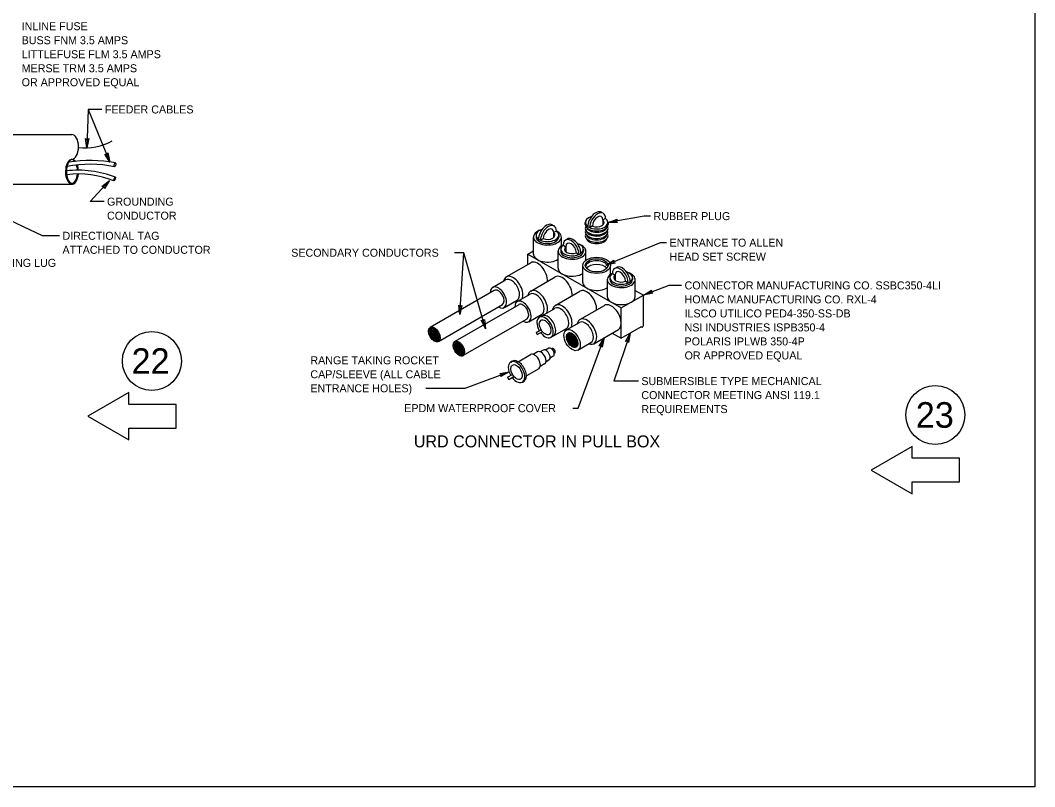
# Model space of a CAD drawing. Extents: x 99981 to 128681, y 99783 to 102182.
# Drawn here: x 127161 to 128681, y 99887 to 101036 of the extents above; entities that cross this region are included whole.
import ezdxf

# ---------------------------------------------------------------- set-up
doc = ezdxf.new("R2010")
doc.units = 0
for name, color, linetype in [('Default', 7, 'Continuous'), ('Level 1', 7, 'Continuous'), ('RD Lighting', 7, 'Continuous')]:
    doc.layers.add(name, color=color, linetype=linetype)

msp = doc.modelspace()

# ---------------------------------------------------------------- linework, layer by layer
at = {"layer": 'Default'}
msp.add_lwpolyline([(125481.4, 102086.3), (128681.1, 102086.3), (128681.1, 99886.7), (125481.4, 99886.7)], close=True, dxfattribs=at)
at = {"layer": 'Level 1'}
for p, q in [((127262.2, 100902.4), (127260.4, 100844.8)), ((127262.2, 100902.4), (127294.8, 100823.1)), ((127282.9, 100902.4), (127262.2, 100902.4)), ((127142.6, 100864.8), (127238.1, 100864.8)), ((127142.6, 100790.3), (127238.1, 100790.3)), ((127265.4, 100764.1), (127294.3, 100795.7)), ((127194, 100712.9), (127081.9, 100765.7)), ((127286.1, 100764.1), (127265.4, 100764.1)), ((128007.4, 100730), (128007.4, 100732.9)), ((128037.8, 100739), (128033.8, 100736.6)), ((128033.8, 100736.6), (128033.8, 100729.1)), ((128095.9, 100742.4), (128041.5, 100732.9)), ((128041.5, 100732.9), (128041.5, 100730)), ((128105.3, 100742.4), (128095.9, 100742.4)), ((127964.1, 100720.1), (127960, 100717.7)), ((127960, 100717.7), (127960, 100710.2)), ((128018, 100727.5), (128014, 100725.1)), ((127219.4, 100712.9), (127194, 100712.9)), ((127929.9, 100685.6), (127929.9, 100711.1)), ((127933.7, 100714), (127933.7, 100711.1)), ((127944.3, 100708.6), (127940.2, 100706.2)), ((127967.8, 100714), (127967.8, 100711.1)), ((127971.6, 100697.6), (127971.6, 100711.1)), ((128119.8, 100702.6), (128038.1, 100668.8)), ((128129.3, 100702.6), (128119.8, 100702.6)), ((127825.2, 100687.5), (127811.2, 100687.5)), ((127819.3, 100594.7), (127825.2, 100687.5)), ((127857.8, 100573.3), (127825.2, 100687.5)), ((127921.3, 100685.6), (127929.9, 100690.5)), ((127921.3, 100670), (127921.3, 100685.6)), ((127921.3, 100685.6), (128061.4, 100604.7)), ((127966.7, 100664.3), (127966.7, 100689.8)), ((127970.6, 100692.7), (127970.6, 100689.8)), ((127974.2, 100698.7), (127978.3, 100696.4)), ((127978.3, 100696.4), (127978.3, 100689)), ((127994.1, 100687.3), (127998.1, 100685)), ((128004.6, 100692.7), (128004.6, 100689.8)), ((128008.5, 100676.3), (128008.5, 100689.8)), ((127888.7, 100651.2), (127925.6, 100672.4)), ((128003.6, 100643), (128003.6, 100668.6)), ((128045.3, 100655), (128045.3, 100668.6)), ((128048, 100656.2), (128052.1, 100653.8)), ((128052.1, 100653.8), (128052.1, 100646.4)), ((127868.4, 100635.4), (127888, 100646.7)), ((127925.6, 100629.9), (127962.4, 100651.2)), ((128040.5, 100621.7), (128040.5, 100647.3)), ((128044.3, 100650.1), (128044.3, 100647.3)), ((128067.8, 100644.7), (128071.9, 100642.4)), ((128078.4, 100650.1), (128078.4, 100647.3)), ((128082.2, 100621.7), (128082.2, 100647.3)), ((128132.9, 100638.5), (128094.5, 100623.9)), ((128151.8, 100638.5), (128132.9, 100638.5)), ((127871, 100630.9), (127775.1, 100575.6)), ((127905.4, 100614.2), (127924.8, 100625.4)), ((127962.4, 100608.6), (127999.3, 100629.9)), ((128061.4, 100604.7), (128094.5, 100623.9)), ((128082.2, 100631), (128094.5, 100623.9)), ((128094.5, 100578.5), (128094.5, 100623.9)), ((127787.3, 100554.5), (127883.2, 100609.8)), ((127907.9, 100609.6), (127811.9, 100554.3)), ((127886.2, 100605.6), (127905.3, 100616.6)), ((127999.3, 100587.3), (128036.2, 100608.6)), ((127922.7, 100584.1), (127942.2, 100595.3)), ((127938.5, 100590.7), (127941.7, 100592.6)), ((127942.5, 100593), (127961.7, 100604.1)), ((128061.4, 100559.3), (128061.4, 100604.7)), ((127824.1, 100533.2), (127920.1, 100588.5)), ((127979.3, 100571.7), (127998.6, 100582.9)), ((127933.7, 100567.9), (127941.1, 100572.2)), ((127933.7, 100567.9), (127935.5, 100564.9)), ((127935.5, 100564.9), (127943.1, 100569.3)), ((127955.9, 100560.7), (127959.9, 100563)), ((127959.9, 100563), (127979.1, 100574)), ((128020.2, 100551.1), (128057.1, 100572.4)), ((128047.9, 100567.1), (128061.4, 100559.3)), ((128074.7, 100567), (128050.1, 100495)), ((128061.4, 100559.3), (128091.7, 100576.9)), ((127996.5, 100541.6), (128016, 100552.8)), ((127996.9, 100454.4), (128035.5, 100560)), ((127907, 100524), (127925.4, 100534.7)), ((127936, 100538.8), (127929.4, 100535)), ((127944.3, 100541.5), (127939.9, 100538.9)), ((127952.6, 100544.3), (127947.8, 100541.5)), ((127959.5, 100532.2), (127954.7, 100529.5)), ((127957.8, 100543.7), (127957.1, 100543.2)), ((127961.6, 100537.1), (127960.8, 100536.6)), ((127895.7, 100523.5), (127898.2, 100524.9)), ((127946.5, 100520.7), (127939.8, 100516.8)), ((127953, 100526.5), (127948.6, 100523.9)), ((127827.2, 100484.2), (127893.2, 100509.1)), ((127891, 100500.7), (127898.3, 100505)), ((127892.8, 100497.6), (127900.4, 100502)), ((127937.6, 100513.5), (127919.2, 100502.9)), ((127891, 100500.7), (127892.8, 100497.6)), ((127913.1, 100493.4), (127915.6, 100494.9)), ((128087, 100495), (128050.1, 100495)), ((127768.4, 100484.2), (127827.2, 100484.2)), ((127988.7, 100454.4), (127996.9, 100454.4))]:
    msp.add_line(p, q, dxfattribs=at)
for points in [[(127263.2, 100858.8), (127260.4, 100844.8), (127258.5, 100859), (127260.8, 100856.7)], [(127291.7, 100837.1), (127294.8, 100823.1), (127287.2, 100835.3), (127290.3, 100834.1)], [(127283, 100786.9), (127294.3, 100795.7), (127286.6, 100783.7), (127286.3, 100786.9)], [(128055.8, 100732.9), (128041.5, 100732.9), (128055, 100737.7), (128053.2, 100734.9)], [(128052, 100672), (128038.1, 100668.8), (128050.2, 100676.4), (128049.1, 100673.4)], [(128108.6, 100626.7), (128094.5, 100623.9), (128106.9, 100631.2), (128105.7, 100628.1)], [(127822.6, 100608.6), (127819.3, 100594.7), (127817.8, 100608.9), (127820, 100606.6)], [(127856.2, 100587.5), (127857.8, 100573.3), (127851.6, 100586.2), (127854.5, 100584.8)], [(128067.9, 100554.4), (128074.7, 100567), (128072.4, 100552.8), (128070.8, 100555.7)], [(128028.4, 100547.5), (128035.5, 100560), (128032.9, 100545.9), (128031.4, 100548.8)], [(127879.2, 100506.4), (127893.2, 100509.1), (127880.9, 100501.9), (127882.1, 100504.9)]]:
    msp.add_lwpolyline(points, close=True, dxfattribs=at)
for centre, radius, start, end in [((127256.7, 100932.6), 87.8, 264.2056, 298.4266), ((127242.7, 100817.2), 11.4, 113.762, 165.0443), ((127265, 100627.8), 198, 78.9111, 99.2947), ((127233.4, 100817), 11.6, 39.1129, 65.8989), ((127247.5, 100660.4), 150.9, 68.3519, 96.7966), ((127247.5, 100660.4), 145.2, 68.3519, 96.856), ((127265, 100627.8), 192.3, 78.9111, 100.276)]:
    msp.add_arc(centre, radius, start, end, dxfattribs=at)
for centre, major_axis, ratio, start_param, end_param in [((127238.1, 100846.3), (0, 18.6), 0.524286, 3.150248, 6.285615), ((127238.1, 100809), (0, 18.6), 0.524286, 5.69971, 10.802617), ((127238.1, 100809), (0, 17.3), 0.486783, 0.869952, 4.499875), ((127238.1, 100809), (0, 17.3), 0.486783, 4.849199, 5.309813), ((127238.1, 100809), (0, 18.6), 0.524286, 4.829653, 5.277118), ((128023.1, 100733.7), (8.4, 14.6), 0.57735, 6.113683, 8.6437), ((128025.9, 100732), (8.4, 14.6), 0.57735, 5.500907, 8.642499), ((127949.3, 100714.8), (8.4, 14.6), 0.57735, 6.113683, 8.6437), ((128024.5, 100732.9), (17, 0), 0.57735, 2.043723, 6.953551), ((128024.5, 100730), (17, 0), 0.57735, 3.141593, 6.283185), ((128025.9, 100732), (5.56, 9.63), 0.57735, 5.501145, 8.639609), ((128024.5, 100732.9), (11.3, 0), 0.57735, 4.106085, 6.89307), ((127950.7, 100711.1), (20.9, 0), 0.57735, 2.164315, 7.164292), ((127950.7, 100714), (17, 0), 0.57735, 2.032674, 6.953551), ((127952.2, 100713.1), (8.4, 14.6), 0.57735, 5.500907, 8.642499), ((127952.2, 100713.1), (5.56, 9.63), 0.57735, 5.501145, 8.639609), ((127950.7, 100714), (11.3, 0), 0.57735, 4.106085, 6.89307), ((128024.5, 100718.7), (17, 0), 0.57735, 2.836673, 6.549804), ((128024.5, 100713), (17, 0), 0.57735, 2.848328, 6.575909), ((128024.5, 100724.3), (17, 0), 0.57735, 2.868704, 6.55622), ((128024.5, 100721.5), (15.6, 0), 0.57735, 3.248585, 6.145478), ((128024.5, 100715.8), (15.6, 0), 0.57735, 3.261904, 6.162161), ((128024.5, 100727.2), (15.6, 0), 0.57735, 3.313023, 6.148611), ((127950.7, 100711.1), (17, 0), 0.57735, 3.141593, 6.283185), ((127950.7, 100711.1), (17, 0), 0.57735, 3.004539, 3.005199), ((127987.6, 100689.8), (20.9, 0), 0.57735, 2.27457, 7.247643), ((127987.6, 100692.7), (17, 0), 0.57735, 2.474262, 7.371716), ((127986.2, 100691.9), (-8.4, 14.6), 0.57735, 3.927123, 7.068716), ((127986.2, 100691.9), (-5.56, 9.63), 0.57735, 3.92676, 7.068352), ((127989.1, 100693.5), (-8.4, 14.6), 0.57735, 3.927123, 6.458478), ((128024.5, 100710.2), (15.6, 0), 0.57735, 3.270531, 6.142887), ((127950.7, 100685.6), (20.9, 0), 0.57735, 3.141593, 5.586889), ((127987.6, 100689.8), (17, 0), 0.57735, 3.141593, 6.283185), ((127987.6, 100689.8), (17, 0), 0.57735, 3.004539, 3.005199), ((127987.6, 100692.7), (11.3, 0), 0.57735, 2.534527, 5.318723), ((127936, 100654.4), (-10.4, 18.1), 0.57735, 3.840254, 6.28365), ((128024.5, 100668.6), (17, 0), 0.57735, 3.004539, 3.005199), ((128024.5, 100665.7), (17, 0), 0.57735, 0.137713, 2.968876), ((128024.5, 100660), (17, 0), 0.57735, 0.449551, 2.696225), ((127899.2, 100633.1), (-10.4, 18.1), 0.57735, 3.511299, 6.867888), ((127972.9, 100633.1), (-10.4, 18.1), 0.57735, 3.840254, 6.28365), ((127987.6, 100664.3), (20.9, 0), 0.57735, 3.141593, 5.586889), ((128061.3, 100647.3), (20.9, 0), 0.57735, 2.26416, 7.252802), ((128061.3, 100650.1), (17, 0), 0.57735, 2.474262, 7.371716), ((128059.9, 100649.3), (-8.4, 14.6), 0.57735, 3.927123, 7.068716), ((128061.3, 100650.1), (11.3, 0), 0.57735, 2.534527, 5.318723), ((128059.9, 100649.3), (-5.56, 9.63), 0.57735, 3.92676, 7.068352), ((128062.8, 100650.9), (-8.4, 14.6), 0.57735, 3.927123, 6.458478), ((127896.7, 100631.7), (-8.7, 15.1), 0.57735, 3.132798, 6.291946), ((128024.5, 100643), (20.9, 0), 0.57735, 3.141593, 5.586889), ((128061.3, 100647.3), (17, 0), 0.57735, 3.141593, 6.283185), ((128061.3, 100647.3), (17, 0), 0.57735, 3.004539, 3.005199), ((127877.1, 100620.4), (-8.7, 15.1), 0.57735, 2.332703, 7.093606), ((127877.1, 100620.4), (-6.1, 10.6), 0.57735, 3.142382, 6.283974), ((127936, 100611.8), (-10.4, 18.1), 0.57735, 3.511299, 6.867888), ((127933.6, 100610.4), (-8.7, 15.1), 0.57735, 3.132798, 6.291946), ((128009.7, 100611.8), (-10.4, 18.1), 0.57735, 3.837363, 6.28365), ((127914, 100599.1), (-8.7, 15.1), 0.57735, 2.369926, 7.104852), ((127899.2, 100633.1), (-10.4, 18.1), 0.57735, 2.550847, 2.771598), ((127914, 100599.1), (-6.1, 10.6), 0.57735, 3.142382, 6.283974), ((127972.9, 100590.5), (-10.4, 18.1), 0.57735, 3.509514, 6.867888), ((128046.6, 100590.5), (-10.4, 18.1), 0.57735, 3.142057, 6.28365), ((128061.3, 100621.7), (20.9, 0), 0.57735, 3.141593, 6.283185), ((127947.2, 100575.7), (-8.7, 15.1), 0.57735, 1.776655, 7.854029), ((127936, 100611.8), (-10.4, 18.1), 0.57735, 2.550847, 2.771598), ((127950.8, 100577.8), (-8.7, 15.1), 0.57735, 3.190548, 6.332665), ((127970.5, 100589.1), (-8.7, 15.1), 0.57735, 3.132798, 6.291946), ((128009.8, 100569.2), (-10.4, 18.1), 0.57735, 2.552288, 6.869338), ((128007.3, 100567.8), (-8.7, 15.1), 0.57735, 3.141603, 6.283196), ((128093.1, 100577.7), (1, 1.74), 0.57735, 2.358489, 5.500082), ((127972.9, 100590.5), (-10.4, 18.1), 0.57735, 2.550847, 2.771598), ((127988.9, 100557.2), (-6.1, 10.6), 0.57735, 0.118401, 3.033391), ((127990.1, 100557.9), (-6.1, 10.6), 0.57735, 0.206652, 2.965468), ((127991.4, 100558.6), (-6.1, 10.6), 0.57735, 0.326201, 2.848852), ((127992.6, 100559.3), (-6.1, 10.6), 0.57735, 0.426417, 2.720117), ((127993.8, 100560.1), (-6.1, 10.6), 0.57735, 0.536288, 2.627234), ((127995.1, 100560.8), (-6.1, 10.6), 0.57735, 0.645059, 2.50346), ((127996.3, 100561.5), (-6.1, 10.6), 0.57735, 0.775948, 2.37161), ((127997.5, 100562.2), (-6.1, 10.6), 0.57735, 0.931064, 2.211843), ((127998.8, 100562.9), (-6.1, 10.6), 0.57735, 1.123825, 2.025294), ((127931.5, 100524.1), (-6.1, 10.6), 0.57735, 3.142382, 6.283974), ((127941.3, 100529.7), (-5.24, 9.07), 0.57735, 3.142596, 6.284189), ((127948.7, 100534), (-4.33, 7.51), 0.57735, 3.141603, 6.283196), ((127956.1, 100538.3), (-3.47, 6.01), 0.57735, 3.139149, 6.280742), ((127959.7, 100540.4), (-1.91, 3.3), 0.57735, 3.141901, 6.283494), ((127904.4, 100508.5), (-8.7, 15.1), 0.57735, 1.776655, 7.854029), ((127906.9, 100509.9), (-8.7, 15), 0.57735, 3.141603, 6.283196)]:
    msp.add_ellipse(centre, major_axis=major_axis, ratio=ratio, start_param=start_param, end_param=end_param, dxfattribs=at)
for centre, major_axis, ratio in [((127302.5, 100819.3), (-0.51, -2.82), 0.388202), ((127302.1, 100798), (1.05, 2.64), 0.311921), ((128024.5, 100668.6), (20.9, 0), 0.57735), ((128024.5, 100668.6), (17, 0), 0.57735), ((127781.2, 100565), (-6.1, 10.6), 0.57735), ((127947.2, 100575.7), (-6.1, 10.6), 0.57735), ((127774.7, 100569.9), (-0.78, 1.34), 0.57735), ((127774.8, 100566.7), (-0.78, 1.34), 0.57735), ((127775.8, 100572.4), (-0.78, 1.34), 0.57735), ((127776.7, 100561.2), (-0.78, 1.34), 0.57735), ((127776.9, 100564.1), (-0.78, 1.34), 0.57735), ((127777.2, 100566.7), (-0.78, 1.34), 0.57735), ((127777.8, 100573.9), (-0.78, 1.34), 0.57735), ((127778.2, 100569.7), (-0.78, 1.34), 0.57735), ((127778.9, 100560.5), (-0.78, 1.34), 0.57735), ((127779.5, 100563.1), (-0.78, 1.34), 0.57735), ((127780, 100565.7), (-0.78, 1.34), 0.57735), ((127780.5, 100570.6), (-0.78, 1.34), 0.57735), ((127780.9, 100573.3), (-0.78, 1.34), 0.57735), ((127781.5, 100568), (-0.78, 1.34), 0.57735), ((127781.5, 100561.5), (-0.78, 1.34), 0.57735), ((127782.4, 100565.2), (-0.78, 1.34), 0.57735), ((127783, 100568.2), (-0.78, 1.34), 0.57735), ((127783.3, 100563), (-0.78, 1.34), 0.57735), ((127783.8, 100570.6), (-0.78, 1.34), 0.57735), ((127784.4, 100564.9), (-0.78, 1.34), 0.57735), ((127785.7, 100561.4), (-0.78, 1.34), 0.57735), ((127786.1, 100567.6), (-0.78, 1.34), 0.57735), ((127786.8, 100563.9), (-0.78, 1.34), 0.57735), ((127788.2, 100560.8), (-0.78, 1.34), 0.57735), ((127987.7, 100556.5), (-8.7, 15.1), 0.57735), ((127987.7, 100556.5), (-6.1, 10.6), 0.57735), ((127779.8, 100557.6), (-0.78, 1.34), 0.57735), ((127781.9, 100556.3), (-0.78, 1.34), 0.57735), ((127782.2, 100559.2), (-0.78, 1.34), 0.57735), ((127784.2, 100559.7), (-0.78, 1.34), 0.57735), ((127784.7, 100556), (-0.78, 1.34), 0.57735), ((127787.4, 100557.5), (-0.78, 1.34), 0.57735), ((127818, 100543.7), (-6.1, 10.6), 0.57735), ((127811.6, 100548.6), (-0.78, 1.34), 0.57735), ((127811.7, 100545.4), (-0.78, 1.34), 0.57735), ((127812.7, 100551.1), (-0.78, 1.34), 0.57735), ((127814, 100545.4), (-0.78, 1.34), 0.57735), ((127814.7, 100552.6), (-0.78, 1.34), 0.57735), ((127815, 100548.4), (-0.78, 1.34), 0.57735), ((127817.4, 100549.3), (-0.78, 1.34), 0.57735), ((127817.7, 100552), (-0.78, 1.34), 0.57735), ((127818.4, 100546.7), (-0.78, 1.34), 0.57735), ((127819.8, 100546.9), (-0.78, 1.34), 0.57735), ((127820.7, 100549.3), (-0.78, 1.34), 0.57735), ((127822.9, 100546.3), (-0.78, 1.34), 0.57735), ((127813.6, 100540.1), (-0.78, 1.34), 0.57735), ((127813.8, 100542.9), (-0.78, 1.34), 0.57735), ((127815.8, 100539.3), (-0.78, 1.34), 0.57735), ((127816.4, 100541.9), (-0.78, 1.34), 0.57735), ((127816.6, 100536.4), (-0.78, 1.34), 0.57735), ((127816.9, 100544.4), (-0.78, 1.34), 0.57735), ((127818.4, 100540.2), (-0.78, 1.34), 0.57735), ((127818.7, 100534.8), (-0.78, 1.34), 0.57735), ((127819.1, 100537.9), (-0.78, 1.34), 0.57735), ((127819.2, 100544), (-0.78, 1.34), 0.57735), ((127820.2, 100541.8), (-0.78, 1.34), 0.57735), ((127821.1, 100538.4), (-0.78, 1.34), 0.57735), ((127821.3, 100543.6), (-0.78, 1.34), 0.57735), ((127821.6, 100534.9), (-0.78, 1.34), 0.57735), ((127822.6, 100540.1), (-0.78, 1.34), 0.57735), ((127823.7, 100542.6), (-0.78, 1.34), 0.57735), ((127824.3, 100536.2), (-0.78, 1.34), 0.57735), ((127825, 100539.5), (-0.78, 1.34), 0.57735), ((127904.4, 100508.5), (-6.1, 10.6), 0.57735)]:
    msp.add_ellipse(centre, major_axis=major_axis, ratio=ratio, dxfattribs=at)
at = {"layer": 'RD Lighting'}
for points in [[(127261.9, 100442.3), (127323.4, 100406.8), (127323.4, 100424.6), (127394.3, 100424.6), (127394.3, 100460.1), (127323.4, 100460.1), (127323.4, 100477.8)], [(128436.1, 100361.5), (128497.5, 100326), (128497.5, 100343.7), (128568.5, 100343.7), (128568.5, 100379.2), (128497.5, 100379.2), (128497.5, 100396.9)]]:
    msp.add_lwpolyline(points, close=True, dxfattribs=at)
for centre in [(127357.8, 100525.1), (128532, 100444.2)]:
    msp.add_circle(centre, 44.2, dxfattribs=at)

# ---------------------------------------------------------------- texts
at = {"layer": 'Level 1'}
for s, height, p in [(' INLINE FUSE ', 12, (127158.2, 101021.2)), (' BUSS FNM 3.5 AMPS', 12, (127158.2, 101000.2)), (' LITTLEFUSE FLM 3.5 AMPS', 12, (127158.2, 100979.2)), (' MERSE TRM 3.5 AMPS', 12, (127158.2, 100958.2)), (' OR APPROVED EQUAL', 12, (127158.2, 100937.2)), (' FEEDER CABLES', 12, (127282.9, 100896.4)), (' GROUNDING ', 12, (127286.1, 100758.1)), (' CONDUCTOR', 12, (127286.1, 100737.1)), (' RUBBER PLUG', 12, (128105.3, 100736.4)), (' DIRECTIONAL TAG', 12, (127219.4, 100706.9)), (' ENTRANCE TO ALLEN', 12, (128129.3, 100696.6)), (' ATTACHED TO CONDUCTOR', 12, (127219.4, 100685.9)), ('SECONDARY CONDUCTORS ', 12, (127566.7, 100681.5)), (' HEAD SET SCREW', 12, (128129.3, 100675.6)), (' GROUNDING LUG', 12, (127072.5, 100666.3)), (' CONNECTOR MANUFACTURING CO. SSBC350-4LI', 12, (128151.8, 100632.5)), (' HOMAC MANUFACTURING CO. RXL-4', 12, (128151.8, 100611.5)), (' ILSCO UTILICO PED4-350-SS-DB', 12, (128151.8, 100590.5)), (' NSI INDUSTRIES ISPB350-4', 12, (128151.8, 100569.5)), (' POLARIS IPLWB 350-4P', 12, (128151.8, 100548.5)), ('RANGE TAKING ROCKET', 12, (127595.4, 100520.2)), (' OR APPROVED EQUAL ', 12, (128151.8, 100527.5)), ('CAP/SLEEVE (ALL CABLE', 12, (127595.4, 100499.2)), ('ENTRANCE HOLES) ', 12, (127595.4, 100478.2)), (' SUBMERSIBLE TYPE MECHANICAL', 12, (128087, 100489)), (' CONNECTOR MEETING ANSI 119.1', 12, (128087, 100468)), ('EPDM WATERPROOF COVER ', 12, (127736.1, 100448.4)), (' REQUIREMENTS', 12, (128087, 100447)), ('URD CONNECTOR IN PULL BOX', 18, (127750.5, 100395.6))]:
    msp.add_text(s, height=height, dxfattribs=at).set_placement(p)
at = {"layer": 'RD Lighting'}
for s, p in [('22', (127327.4, 100505.9)), ('23', (128502.8, 100425.1))]:
    msp.add_text(s, height=38.31, dxfattribs=at).set_placement(p)

doc.saveas('drawing.dxf')
